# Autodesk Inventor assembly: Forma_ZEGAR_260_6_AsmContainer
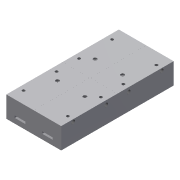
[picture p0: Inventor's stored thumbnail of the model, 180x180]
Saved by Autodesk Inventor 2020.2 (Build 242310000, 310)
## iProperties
Created: 2015-01
Part Number: Forma_ZEGAR_260_6_AsmContainer
Document SubType Name: Assembly
Designer: F.Stasiak
Catalog Web Link: www.expertbooks.pl
Manager: www.cadconsulting.pl
Company: Fabian Stasiak CAD Consulting
Author: F.Stasiak
Subject: Zbiór ćwiczeń. Autodesk Inventor 2020. Kurs Professional
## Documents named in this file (9)
- C:\2020_Kurs_Professional\R6 Formy\Komponenty\Forma_ZEGAR_260_6_AsmContainer.iam
- C:\2020_Kurs_Professional\R6 Formy\Komponenty\Forma_ZEGAR_260_6_ZEGAR_260_CR_1.ipt
- C:\2020_Kurs_Professional\R6 Formy\Komponenty\Forma_ZEGAR_260_6_ZEGAR_260_CV_1.ipt
- C:\2020_Kurs_Professional\R6 Formy\Komponenty\Forma_ZEGAR_260_6_ZEGAR_260_CR_2.ipt
- C:\2020_Kurs_Professional\R6 Formy\Komponenty\Forma_ZEGAR_260_6_ZEGAR_260_CV_2.ipt
- C:\2020_Kurs_Professional\R6 Formy\Komponenty\Forma_ZEGAR_260_6_ZEGAR_260_CR_3.ipt
- C:\2020_Kurs_Professional\R6 Formy\Komponenty\Forma_ZEGAR_260_6_ZEGAR_260_CV_3.ipt
- C:\2020_Kurs_Professional\R6 Formy\Komponenty\Forma_ZEGAR_260_6_ZEGAR_260_CR_4.ipt
- C:\2020_Kurs_Professional\R6 Formy\Komponenty\Forma_ZEGAR_260_6_ZEGAR_260_CV_4.ipt
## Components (8 placed, 8 different names)
1. Forma_ZEGAR_260_4_ZEGAR_260_CR_1:1
2. Forma_ZEGAR_260_4_ZEGAR_260_CV_1:1
3. Forma_ZEGAR_260_4_ZEGAR_260_CR_2:1
4. Forma_ZEGAR_260_4_ZEGAR_260_CV_2:1
5. Forma_ZEGAR_260_4_ZEGAR_260_CR_3:1
6. Forma_ZEGAR_260_4_ZEGAR_260_CV_3:1
7. Forma_ZEGAR_260_4_ZEGAR_260_CR_4:1
8. Forma_ZEGAR_260_4_ZEGAR_260_CV_4:1
